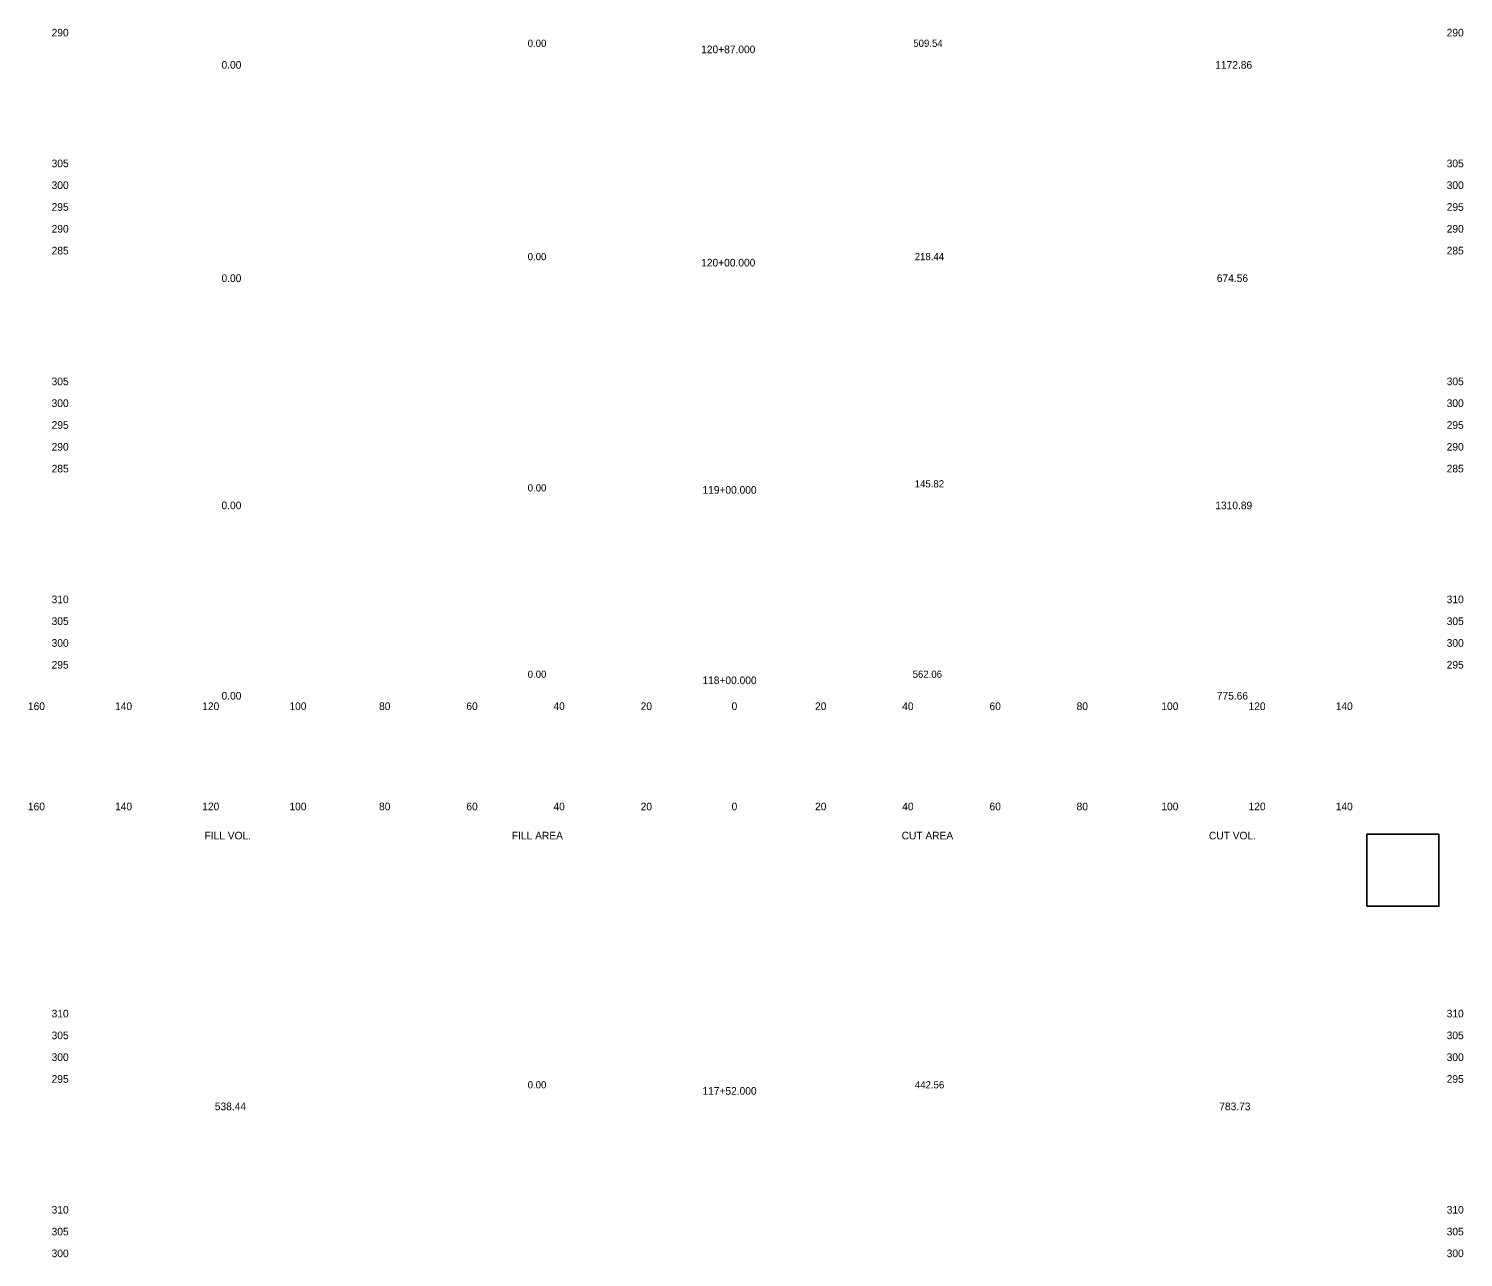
# Model space of a CAD drawing. Extents: x 21477 to 21806, y 6470 to 11049.
# Drawn here: x 21477.1 to 21806.1, y 8184.8 to 8466.6 of the extents above; entities that cross this region are included whole.
import ezdxf

# ---------------------------------------------------------------- set-up
doc = ezdxf.new("R2010")
doc.units = 0
for name, color, linetype in [('SHEET_CONSULTANT_STAMP', 7, 'Continuous'), ('XS_SHEET_EW_TX_AREA', 7, 'Continuous'), ('XS_SHEET_EW_TX_VOLUME', 7, 'Continuous'), ('XS_SHEET_LABELS_ELEVATION', 7, 'Continuous'), ('XS_SHEET_LABELS_OFFSET', 7, 'Continuous'), ('XS_SHEET_LABELS_STATION', 7, 'Continuous'), ('XS_SHEET_TX', 7, 'Continuous')]:
    doc.layers.add(name, color=color, linetype=linetype)

msp = doc.modelspace()

# ---------------------------------------------------------------- linework, layer by layer
at = {"layer": 'SHEET_CONSULTANT_STAMP'}
msp.add_lwpolyline([(21784.04, 8265.34), (21800.54, 8265.34), (21800.54, 8281.84), (21784.04, 8281.84)], close=True, dxfattribs=at)

# ---------------------------------------------------------------- texts
at = {"layer": 'XS_SHEET_EW_TX_AREA'}
for s, p in [(' 0.00 ', (21590.92, 8462.44)), (' 509.54 ', (21679.37, 8462.44)), (' 0.00 ', (21590.92, 8413.52)), (' 218.44 ', (21679.7, 8413.52)), (' 0.00 ', (21590.92, 8360.47)), (' 145.82 ', (21679.7, 8361.4)), (' 0.00 ', (21590.92, 8317.73)), (' 562.06 ', (21679.22, 8317.73)), (' 0.00 ', (21590.92, 8223.55)), ('442.56 ', (21680.35, 8223.55))]:
    msp.add_text(s, height=1.65, dxfattribs=at).set_placement(p)
at = {"layer": 'XS_SHEET_EW_TX_VOLUME'}
for s, p in [(' 0.00 ', (21520.66, 8457.44)), (' 1172.86 ', (21748.6, 8457.44)), (' 0.00 ', (21520.66, 8408.52)), (' 674.56 ', (21748.96, 8408.52)), (' 0.00 ', (21520.66, 8356.4)), (' 1310.89 ', (21748.61, 8356.4)), (' 0.00 ', (21520.66, 8312.73)), (' 775.66 ', (21748.96, 8312.73)), (' 538.44 ', (21519.12, 8218.55)), ('783.73', (21750.17, 8218.55))]:
    msp.add_text(s, height=1.75, dxfattribs=at).set_placement(p)
at = {"layer": 'XS_SHEET_LABELS_ELEVATION'}
for s, p in [('  290  ', (21481.04, 8464.84)), ('  290  ', (21801.04, 8464.84)), ('  305  ', (21481.04, 8434.84)), ('  305  ', (21801.04, 8434.84)), ('  300  ', (21481.04, 8429.84)), ('  300  ', (21801.04, 8429.84)), ('  295  ', (21481.04, 8424.84)), ('  295  ', (21801.04, 8424.84)), ('  290  ', (21481.04, 8419.84)), ('  290  ', (21801.04, 8419.84)), ('  285  ', (21481.04, 8414.84)), ('  285  ', (21801.04, 8414.84)), ('  305  ', (21481.04, 8384.84)), ('  305  ', (21801.04, 8384.84)), ('  300  ', (21481.04, 8379.84)), ('  300  ', (21801.04, 8379.84)), ('  295  ', (21481.04, 8374.84)), ('  295  ', (21801.04, 8374.84)), ('  290  ', (21481.04, 8369.84)), ('  290  ', (21801.04, 8369.84)), ('  285  ', (21481.04, 8364.84)), ('  285  ', (21801.04, 8364.84)), ('  310  ', (21481.04, 8334.84)), ('  310  ', (21801.04, 8334.84)), ('  305  ', (21481.04, 8329.84)), ('  305  ', (21801.04, 8329.84)), ('  300  ', (21481.04, 8324.84)), ('  300  ', (21801.04, 8324.84)), ('  295  ', (21481.04, 8319.84)), ('  295  ', (21801.04, 8319.84)), ('  310  ', (21481.04, 8239.84)), ('  310  ', (21801.04, 8239.84)), ('  305  ', (21481.04, 8234.84)), ('  305  ', (21801.04, 8234.84)), ('  300  ', (21481.04, 8229.84)), ('  300  ', (21801.04, 8229.84)), ('  295  ', (21481.04, 8224.84)), ('  295  ', (21801.04, 8224.84)), ('  310  ', (21481.04, 8194.84)), ('  310  ', (21801.04, 8194.84)), ('  305  ', (21481.04, 8189.84)), ('  305  ', (21801.04, 8189.84)), ('  300  ', (21481.04, 8184.84)), ('  300  ', (21801.04, 8184.84))]:
    msp.add_text(s, height=1.75, dxfattribs=at).set_placement(p)
at = {"layer": 'XS_SHEET_LABELS_OFFSET'}
for s, p in [('  160  ', (21475.6, 8310.34)), ('  140  ', (21495.59, 8310.34)), ('  120  ', (21515.59, 8310.34)), ('  100  ', (21535.59, 8310.34)), ('  80  ', (21556.15, 8310.34)), ('  60  ', (21576.17, 8310.34)), ('  40  ', (21596.15, 8310.34)), ('  20  ', (21616.15, 8310.34)), ('  0  ', (21637.01, 8310.34)), ('  0  ', (21637.01, 8310.34)), ('  20  ', (21656.15, 8310.34)), ('  40  ', (21676.15, 8310.34)), ('  60  ', (21696.17, 8310.34)), ('  80  ', (21716.15, 8310.34)), ('  100  ', (21735.59, 8310.34)), ('  120  ', (21755.59, 8310.34)), ('  140  ', (21775.59, 8310.34)), ('  160  ', (21475.6, 8287.34)), ('  140  ', (21495.59, 8287.34)), ('  120  ', (21515.59, 8287.34)), ('  100  ', (21535.59, 8287.34)), ('  80  ', (21556.15, 8287.34)), ('  60  ', (21576.17, 8287.34)), ('  40  ', (21596.15, 8287.34)), ('  20  ', (21616.15, 8287.34)), ('  0  ', (21637.01, 8287.34)), ('  0  ', (21637.01, 8287.34)), ('  20  ', (21656.15, 8287.34)), ('  40  ', (21676.15, 8287.34)), ('  60  ', (21696.17, 8287.34)), ('  80  ', (21716.15, 8287.34)), ('  100  ', (21735.59, 8287.34)), ('  120  ', (21755.59, 8287.34)), ('  140  ', (21775.59, 8287.34))]:
    msp.add_text(s, height=1.75, dxfattribs=at).set_placement(p)
at = {"layer": 'XS_SHEET_LABELS_STATION'}
for s, p in [('  120+87.000  ', (21630.03, 8460.99)), ('  120+00.000  ', (21630.03, 8412.07)), ('  119+00.000  ', (21630.32, 8359.95)), ('  118+00.000  ', (21630.32, 8316.28)), ('  117+52.000  ', (21630.32, 8222.1))]:
    msp.add_text(s, height=1.75, dxfattribs=at).set_placement(p)
at = {"layer": 'XS_SHEET_TX'}
for s, p in [('FILL VOL.', (21517.41, 8280.67)), ('FILL AREA', (21587.92, 8280.67)), ('CUT AREA', (21677.31, 8280.67)), ('CUT VOL.', (21747.8, 8280.67))]:
    msp.add_text(s, height=1.75, dxfattribs=at).set_placement(p)

doc.saveas('drawing.dxf')
